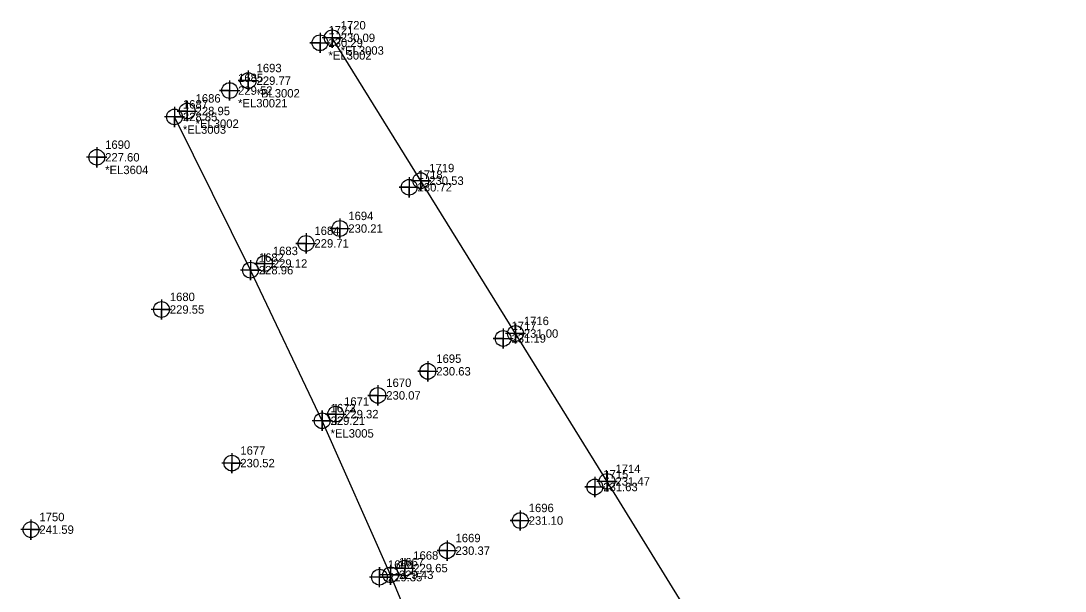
# Model space of a CAD drawing. Extents: x 2130621 to 2131998, y 642516 to 644503.
# Drawn here: x 2130959.7 to 2131269.8, y 644036.8 to 644206.1 of the extents above; entities that cross this region are included whole.
import ezdxf

# ---------------------------------------------------------------- set-up
doc = ezdxf.new("R2010")
doc.units = 0
for name, color, linetype in [('Exist Other Culture Fence Line Cogo Elevation', 7, 'Continuous'), ('Exist Other Culture Fence Line Cogo Number', 7, 'Continuous'), ('Exist Other Culture Fence Line Cogo Point CELL', 7, 'Continuous'), ('Exist Roads EOP', 7, 'Continuous'), ('Exist Roads EOP Other Cogo Comment', 7, 'Continuous'), ('Exist Roads EOP Other Cogo Elevation', 7, 'Continuous'), ('Exist Roads EOP Other Cogo Number', 7, 'Continuous'), ('Exist Roads EOP Other Cogo Point CELL', 7, 'Continuous'), ('Exist Roads EOT Cogo Comment', 7, 'Continuous'), ('Exist Roads EOT Cogo Elevation', 7, 'Continuous'), ('Exist Roads EOT Cogo Number', 7, 'Continuous'), ('Exist Roads EOT Cogo Point CELL', 7, 'Continuous'), ('Exist Roads Soil Cogo Comment', 7, 'Continuous'), ('Exist Roads Soil Cogo Elevation', 7, 'Continuous'), ('Exist Roads Soil Cogo Number', 7, 'Continuous'), ('Exist Roads Soil Cogo Point CELL', 7, 'Continuous'), ('Exist Vegetation Woods Line Cogo Comment', 7, 'Continuous'), ('Exist Vegetation Woods Line Cogo Elevation', 7, 'Continuous'), ('Exist Vegetation Woods Line Cogo Number', 7, 'Continuous'), ('Exist Vegetation Woods Line Cogo Point CELL', 7, 'Continuous')]:
    doc.layers.add(name, color=color, linetype=linetype)

msp = doc.modelspace()

# ---------------------------------------------------------------- linework, layer by layer
at = {"layer": 'Exist Other Culture Fence Line Cogo Point CELL'}
msp.add_lwpolyline([(2130962.67, 644058.06), (2130962.67, 644052.06), (2130962.67, 644055.06), (2130965.67, 644055.06), (2130959.67, 644055.06)], dxfattribs=at)
msp.add_circle((2130962.67, 644055.06), 2.34, dxfattribs=at)
at = {"layer": 'Exist Roads EOP'}
for points in [[(2131269.83, 643849.54), (2131245.23, 643889.35), (2131216.18, 643936.13), (2131188.66, 643980.63), (2131160.56, 644026.02), (2131133.77, 644069.38), (2131106.56, 644113.29), (2131078.46, 644158.69), (2131052.15, 644201.1)], [(2131091.53, 643988.04), (2131088.18, 643996.52), (2131069.48, 644041.65), (2131049.16, 644087.39), (2131027.85, 644132.11), (2131005.29, 644177.62)]]:
    msp.add_lwpolyline(points, dxfattribs=at)
at = {"layer": 'Exist Roads EOP Other Cogo Point CELL'}
for points in [[(2131052.15, 644204.1), (2131052.15, 644198.1), (2131052.15, 644201.1), (2131055.15, 644201.1), (2131049.15, 644201.1)], [(2131005.29, 644180.62), (2131005.29, 644174.62), (2131005.29, 644177.62), (2131008.29, 644177.62), (2131002.29, 644177.62)], [(2131078.46, 644161.69), (2131078.46, 644155.69), (2131078.46, 644158.69), (2131081.46, 644158.69), (2131075.46, 644158.69)], [(2131027.85, 644135.11), (2131027.85, 644129.11), (2131027.85, 644132.11), (2131030.85, 644132.11), (2131024.85, 644132.11)], [(2131106.56, 644116.29), (2131106.56, 644110.29), (2131106.56, 644113.29), (2131109.56, 644113.29), (2131103.56, 644113.29)], [(2131049.16, 644090.39), (2131049.16, 644084.39), (2131049.16, 644087.39), (2131052.16, 644087.39), (2131046.16, 644087.39)], [(2131133.77, 644072.38), (2131133.77, 644066.38), (2131133.77, 644069.38), (2131136.77, 644069.38), (2131130.77, 644069.38)], [(2131069.48, 644044.65), (2131069.48, 644038.65), (2131069.48, 644041.65), (2131072.48, 644041.65), (2131066.48, 644041.65)]]:
    msp.add_lwpolyline(points, dxfattribs=at)
for centre in [(2131052.15, 644201.1), (2131005.29, 644177.62), (2131078.46, 644158.69), (2131027.85, 644132.11), (2131106.56, 644113.29), (2131049.16, 644087.39), (2131133.77, 644069.38), (2131069.48, 644041.65)]:
    msp.add_circle(centre, 2.34, dxfattribs=at)
at = {"layer": 'Exist Roads EOT Cogo Point CELL'}
for points in [[(2131048.52, 644202.64), (2131048.52, 644196.64), (2131048.52, 644199.64), (2131045.52, 644199.64), (2131051.52, 644199.64)], [(2131027.18, 644191.39), (2131027.18, 644185.39), (2131027.18, 644188.39), (2131024.18, 644188.39), (2131030.18, 644188.39)], [(2131021.68, 644188.45), (2131021.68, 644182.45), (2131021.68, 644185.45), (2131018.68, 644185.45), (2131024.68, 644185.45)], [(2131009.06, 644182.38), (2131009.06, 644176.38), (2131009.06, 644179.38), (2131006.06, 644179.38), (2131012.06, 644179.38)], [(2131074.99, 644159.73), (2131074.99, 644153.73), (2131074.99, 644156.73), (2131071.99, 644156.73), (2131077.99, 644156.73)], [(2131054.43, 644147.48), (2131054.43, 644141.48), (2131054.43, 644144.48), (2131051.43, 644144.48), (2131057.43, 644144.48)], [(2131044.36, 644143.06), (2131044.36, 644137.06), (2131044.36, 644140.06), (2131041.36, 644140.06), (2131047.36, 644140.06)], [(2131032.01, 644137.09), (2131032.01, 644131.09), (2131032.01, 644134.09), (2131029.01, 644134.09), (2131035.01, 644134.09)], [(2131102.9, 644114.83), (2131102.9, 644108.83), (2131102.9, 644111.83), (2131099.9, 644111.83), (2131105.9, 644111.83)], [(2131080.56, 644105.08), (2131080.56, 644099.08), (2131080.56, 644102.08), (2131077.56, 644102.08), (2131083.56, 644102.08)], [(2131065.7, 644097.92), (2131065.7, 644091.92), (2131065.7, 644094.92), (2131062.7, 644094.92), (2131068.7, 644094.92)], [(2131053.17, 644092.36), (2131053.17, 644086.36), (2131053.17, 644089.36), (2131050.17, 644089.36), (2131056.17, 644089.36)], [(2131130.15, 644070.72), (2131130.15, 644064.72), (2131130.15, 644067.72), (2131127.15, 644067.72), (2131133.15, 644067.72)], [(2131108.01, 644060.75), (2131108.01, 644054.75), (2131108.01, 644057.75), (2131105.01, 644057.75), (2131111.01, 644057.75)], [(2131086.27, 644051.81), (2131086.27, 644045.81), (2131086.27, 644048.81), (2131083.27, 644048.81), (2131089.27, 644048.81)], [(2131073.72, 644046.63), (2131073.72, 644040.63), (2131073.72, 644043.63), (2131070.72, 644043.63), (2131076.72, 644043.63)]]:
    msp.add_lwpolyline(points, dxfattribs=at)
for centre in [(2131048.52, 644199.64), (2131027.18, 644188.39), (2131021.68, 644185.45), (2131009.06, 644179.38), (2131074.99, 644156.73), (2131054.43, 644144.48), (2131044.36, 644140.06), (2131032.01, 644134.09), (2131102.9, 644111.83), (2131080.56, 644102.08), (2131065.7, 644094.92), (2131053.17, 644089.36), (2131130.15, 644067.72), (2131108.01, 644057.75), (2131086.27, 644048.81), (2131073.72, 644043.63)]:
    msp.add_circle(centre, 2.34, dxfattribs=at)
at = {"layer": 'Exist Roads Soil Cogo Point CELL'}
for points in [[(2131049.15, 644084.39), (2131049.15, 644090.39), (2131049.15, 644087.39), (2131052.15, 644087.39), (2131046.15, 644087.39)], [(2131066.19, 644037.95), (2131066.19, 644043.95), (2131066.19, 644040.95), (2131069.19, 644040.95), (2131063.19, 644040.95)]]:
    msp.add_lwpolyline(points, dxfattribs=at)
for centre in [(2131049.15, 644087.39), (2131066.19, 644040.95)]:
    msp.add_circle(centre, 2.34, dxfattribs=at)
at = {"layer": 'Exist Vegetation Woods Line Cogo Point CELL'}
for points in [[(2130982.2, 644168.64), (2130982.2, 644162.64), (2130982.2, 644165.64), (2130985.2, 644165.64), (2130979.2, 644165.64)], [(2131001.41, 644123.43), (2131001.41, 644117.43), (2131001.41, 644120.43), (2131004.41, 644120.43), (2130998.41, 644120.43)], [(2131022.35, 644077.81), (2131022.35, 644071.81), (2131022.35, 644074.81), (2131025.35, 644074.81), (2131019.35, 644074.81)]]:
    msp.add_lwpolyline(points, dxfattribs=at)
for centre in [(2130982.2, 644165.64), (2131001.41, 644120.43), (2131022.35, 644074.81)]:
    msp.add_circle(centre, 2.34, dxfattribs=at)

# ---------------------------------------------------------------- texts
at = {"layer": 'Exist Other Culture Fence Line Cogo Elevation'}
msp.add_text('241.59', height=2.5, dxfattribs=at).set_placement((2130965.17, 644053.81))
at = {"layer": 'Exist Other Culture Fence Line Cogo Number'}
msp.add_text('1750', height=2.5, dxfattribs=at).set_placement((2130965.17, 644057.56))
at = {"layer": 'Exist Roads EOP Other Cogo Comment'}
for p in [(2131054.65, 644196.1), (2131007.79, 644172.62)]:
    msp.add_text('*EL3003', height=2.5, dxfattribs=at).set_placement(p)
at = {"layer": 'Exist Roads EOP Other Cogo Elevation'}
for s, p in [('230.09', (2131054.65, 644199.85)), ('228.85', (2131007.79, 644176.37)), ('230.53', (2131080.96, 644157.44)), ('228.96', (2131030.35, 644130.86)), ('231.00', (2131109.06, 644112.04)), ('229.21', (2131051.66, 644086.14)), ('231.47', (2131136.27, 644068.13)), ('229.43', (2131071.98, 644040.4))]:
    msp.add_text(s, height=2.5, dxfattribs=at).set_placement(p)
at = {"layer": 'Exist Roads EOP Other Cogo Number'}
for s, p in [('1720', (2131054.65, 644203.6)), ('1687', (2131007.79, 644180.12)), ('1719', (2131080.96, 644161.19)), ('1682', (2131030.35, 644134.61)), ('1716', (2131109.06, 644115.79)), ('1672', (2131051.66, 644089.89)), ('1714', (2131136.27, 644071.88)), ('1667', (2131071.98, 644044.15))]:
    msp.add_text(s, height=2.5, dxfattribs=at).set_placement(p)
at = {"layer": 'Exist Roads EOT Cogo Comment'}
for s, p in [('*EL3002', (2131051.02, 644194.64)), ('*BL3002', (2131029.68, 644183.39)), ('*EL30021', (2131024.18, 644180.45)), ('*EL3002', (2131011.56, 644174.38))]:
    msp.add_text(s, height=2.5, dxfattribs=at).set_placement(p)
at = {"layer": 'Exist Roads EOT Cogo Elevation'}
for s, p in [('230.29', (2131051.02, 644198.39)), ('229.77', (2131029.68, 644187.14)), ('229.52', (2131024.18, 644184.2)), ('228.95', (2131011.56, 644178.13)), ('230.72', (2131077.49, 644155.48)), ('230.21', (2131056.93, 644143.23)), ('229.71', (2131046.86, 644138.81)), ('229.12', (2131034.51, 644132.84)), ('231.19', (2131105.4, 644110.58)), ('230.63', (2131083.06, 644100.83)), ('230.07', (2131068.2, 644093.67)), ('229.32', (2131055.67, 644088.11)), ('231.63', (2131132.65, 644066.47)), ('231.10', (2131110.51, 644056.5)), ('230.37', (2131088.77, 644047.56)), ('229.65', (2131076.22, 644042.38))]:
    msp.add_text(s, height=2.5, dxfattribs=at).set_placement(p)
at = {"layer": 'Exist Roads EOT Cogo Number'}
for s, p in [('1721', (2131051.02, 644202.14)), ('1693', (2131029.68, 644190.89)), ('1685', (2131024.18, 644187.95)), ('1686', (2131011.56, 644181.88)), ('1718', (2131077.49, 644159.23)), ('1694', (2131056.93, 644146.98)), ('1684', (2131046.86, 644142.56)), ('1683', (2131034.51, 644136.59)), ('1717', (2131105.4, 644114.33)), ('1695', (2131083.06, 644104.58)), ('1670', (2131068.2, 644097.42)), ('1671', (2131055.67, 644091.86)), ('1715', (2131132.65, 644070.22)), ('1696', (2131110.51, 644060.25)), ('1669', (2131088.77, 644051.31)), ('1668', (2131076.22, 644046.13))]:
    msp.add_text(s, height=2.5, dxfattribs=at).set_placement(p)
at = {"layer": 'Exist Roads Soil Cogo Comment'}
msp.add_text('*EL3005', height=2.5, dxfattribs=at).set_placement((2131051.65, 644082.39))
at = {"layer": 'Exist Roads Soil Cogo Elevation'}
for s, p in [('229.21', (2131051.65, 644086.14)), ('229.35', (2131068.69, 644039.7))]:
    msp.add_text(s, height=2.5, dxfattribs=at).set_placement(p)
at = {"layer": 'Exist Roads Soil Cogo Number'}
for s, p in [('1673', (2131051.65, 644089.89)), ('1666', (2131068.69, 644043.45))]:
    msp.add_text(s, height=2.5, dxfattribs=at).set_placement(p)
at = {"layer": 'Exist Vegetation Woods Line Cogo Comment'}
msp.add_text('*EL3604', height=2.5, dxfattribs=at).set_placement((2130984.7, 644160.64))
at = {"layer": 'Exist Vegetation Woods Line Cogo Elevation'}
for s, p in [('227.60', (2130984.7, 644164.39)), ('229.55', (2131003.91, 644119.18)), ('230.52', (2131024.85, 644073.56))]:
    msp.add_text(s, height=2.5, dxfattribs=at).set_placement(p)
at = {"layer": 'Exist Vegetation Woods Line Cogo Number'}
for s, p in [('1690', (2130984.7, 644168.14)), ('1680', (2131003.91, 644122.93)), ('1677', (2131024.85, 644077.31))]:
    msp.add_text(s, height=2.5, dxfattribs=at).set_placement(p)

doc.saveas('drawing.dxf')
